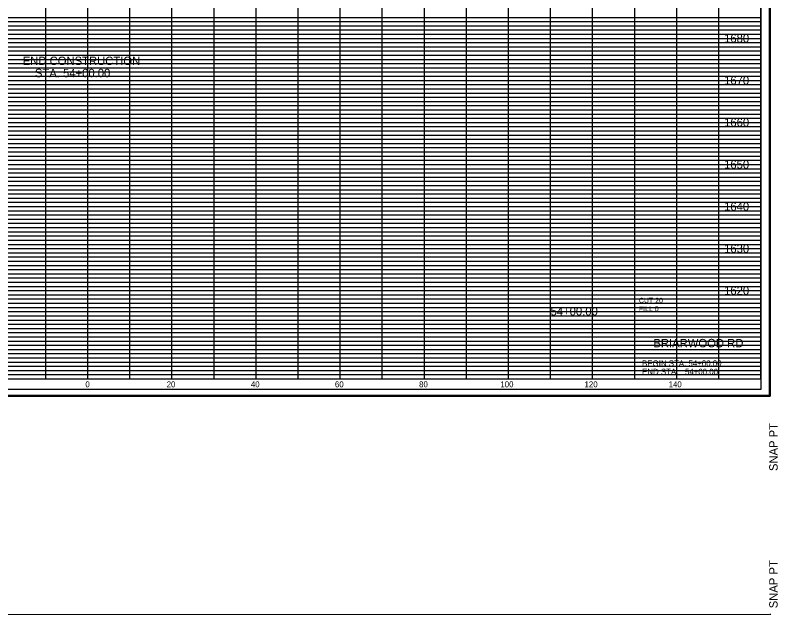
# Model space of a CAD drawing. Extents: x 980 to 2228, y 978 to 2394.
# Drawn here: x 1142.7 to 1324, y 2025.5 to 2166.5 of the extents above; entities that cross this region are included whole.
import ezdxf

# ---------------------------------------------------------------- set-up
doc = ezdxf.new("R2010")
doc.units = 0
for name, color, linetype in [('DESIGN - SHEET - Corner Text', 7, 'Continuous'), ('DESIGN - SHEET - Light Grid', 7, 'Continuous'), ('DESIGN - SHEET - Linework', 7, 'Continuous'), ('DESIGN - SHEET - Plot Shape', 7, 'Continuous'), ('DESIGN - TYPICAL - Finished Grade and Subgrade', 7, 'Continuous'), ('DESIGN - TYPICAL - Text', 7, 'Continuous')]:
    doc.layers.add(name, color=color, linetype=linetype)

# ---------------------------------------------------------------- blocks, each defined once
blk = doc.blocks.new('XSTSHT')
at = {"layer": 'DESIGN - SHEET - Light Grid'}
for p, q in [((8, 8.6), (16, 8.6)), ((16, 8.6), (24, 8.6)), ((24, 8.6), (32, 8.6)), ((8, 8.5), (16, 8.5)), ((8, 8.4), (16, 8.4)), ((16, 8.5), (24, 8.5)), ((16, 8.4), (24, 8.4)), ((24, 8.5), (32, 8.5)), ((24, 8.4), (32, 8.4)), ((8, 8.3), (16, 8.3)), ((8, 8.2), (16, 8.2)), ((16, 8.3), (24, 8.3)), ((16, 8.2), (24, 8.2)), ((24, 8.3), (32, 8.3)), ((24, 8.2), (32, 8.2)), ((8, 8.1), (16, 8.1)), ((16, 8.1), (24, 8.1)), ((24, 8.1), (32, 8.1)), ((8, 7.9), (16, 7.9)), ((8, 7.8), (16, 7.8)), ((16, 7.9), (24, 7.9)), ((16, 7.8), (24, 7.8)), ((24, 7.9), (32, 7.9)), ((24, 7.8), (32, 7.8)), ((8, 7.7), (16, 7.7)), ((16, 7.7), (24, 7.7)), ((24, 7.7), (32, 7.7)), ((8, 7.6), (16, 7.6)), ((8, 7.5), (16, 7.5)), ((16, 7.6), (24, 7.6)), ((16, 7.5), (24, 7.5)), ((24, 7.6), (32, 7.6)), ((24, 7.5), (32, 7.5)), ((8, 7.4), (16, 7.4)), ((8, 7.3), (16, 7.3)), ((16, 7.4), (24, 7.4)), ((16, 7.3), (24, 7.3)), ((24, 7.4), (32, 7.4)), ((24, 7.3), (32, 7.3)), ((8, 7.2), (16, 7.2)), ((8, 7.1), (16, 7.1)), ((16, 7.2), (24, 7.2)), ((16, 7.1), (24, 7.1)), ((24, 7.2), (32, 7.2)), ((24, 7.1), (32, 7.1)), ((8, 6.9), (16, 6.9)), ((16, 6.9), (24, 6.9)), ((24, 6.9), (32, 6.9)), ((8, 6.8), (16, 6.8)), ((16, 6.8), (24, 6.8)), ((24, 6.8), (32, 6.8)), ((8, 6.7), (16, 6.7)), ((8, 6.6), (16, 6.6)), ((16, 6.7), (24, 6.7)), ((16, 6.6), (24, 6.6)), ((24, 6.7), (32, 6.7)), ((24, 6.6), (32, 6.6)), ((8, 6.5), (16, 6.5)), ((8, 6.4), (16, 6.4)), ((16, 6.5), (24, 6.5)), ((16, 6.4), (24, 6.4)), ((24, 6.5), (32, 6.5)), ((24, 6.4), (32, 6.4)), ((8, 6.3), (16, 6.3)), ((8, 6.2), (16, 6.2)), ((16, 6.3), (24, 6.3)), ((16, 6.2), (24, 6.2)), ((24, 6.3), (32, 6.3)), ((24, 6.2), (32, 6.2)), ((8, 6.1), (16, 6.1)), ((16, 6.1), (24, 6.1)), ((24, 6.1), (32, 6.1)), ((8, 5.9), (16, 5.9)), ((16, 5.9), (24, 5.9)), ((24, 5.9), (32, 5.9)), ((8, 5.8), (16, 5.8)), ((8, 5.7), (16, 5.7)), ((16, 5.8), (24, 5.8)), ((16, 5.7), (24, 5.7)), ((24, 5.8), (32, 5.8)), ((24, 5.7), (32, 5.7)), ((8, 5.6), (16, 5.6)), ((8, 5.5), (16, 5.5)), ((16, 5.6), (24, 5.6)), ((16, 5.5), (24, 5.5)), ((24, 5.6), (32, 5.6)), ((24, 5.5), (32, 5.5)), ((8, 5.4), (16, 5.4)), ((8, 5.3), (16, 5.3)), ((16, 5.4), (24, 5.4)), ((16, 5.3), (24, 5.3)), ((24, 5.4), (32, 5.4)), ((24, 5.3), (32, 5.3)), ((8, 5.2), (16, 5.2)), ((8, 5.1), (16, 5.1)), ((16, 5.2), (24, 5.2)), ((16, 5.1), (24, 5.1)), ((24, 5.2), (32, 5.2)), ((24, 5.1), (32, 5.1)), ((8, 4.9), (16, 4.9)), ((16, 4.9), (24, 4.9)), ((24, 4.9), (32, 4.9)), ((8, 4.8), (16, 4.8)), ((16, 4.8), (24, 4.8)), ((24, 4.8), (32, 4.8)), ((8, 4.7), (16, 4.7)), ((8, 4.6), (16, 4.6)), ((16, 4.7), (24, 4.7)), ((16, 4.6), (24, 4.6)), ((24, 4.7), (32, 4.7)), ((24, 4.6), (32, 4.6)), ((8, 4.5), (16, 4.5)), ((8, 4.4), (16, 4.4)), ((16, 4.5), (24, 4.5)), ((16, 4.4), (24, 4.4)), ((24, 4.5), (32, 4.5)), ((24, 4.4), (32, 4.4)), ((8, 4.3), (16, 4.3)), ((8, 4.2), (16, 4.2)), ((16, 4.3), (24, 4.3)), ((16, 4.2), (24, 4.2)), ((24, 4.3), (32, 4.3)), ((24, 4.2), (32, 4.2)), ((8, 4.1), (16, 4.1)), ((16, 4.1), (24, 4.1)), ((24, 4.1), (32, 4.1)), ((8, 3.9), (16, 3.9)), ((16, 3.9), (24, 3.9)), ((24, 3.9), (32, 3.9)), ((8, 3.8), (16, 3.8)), ((8, 3.7), (16, 3.7)), ((16, 3.8), (24, 3.8)), ((16, 3.7), (24, 3.7)), ((24, 3.8), (32, 3.8)), ((24, 3.7), (32, 3.7)), ((8, 3.6), (16, 3.6)), ((8, 3.5), (16, 3.5)), ((16, 3.6), (24, 3.6)), ((16, 3.5), (24, 3.5)), ((24, 3.6), (32, 3.6)), ((24, 3.5), (32, 3.5)), ((8, 3.4), (16, 3.4)), ((8, 3.3), (16, 3.3)), ((16, 3.4), (24, 3.4)), ((16, 3.3), (24, 3.3)), ((24, 3.4), (32, 3.4)), ((24, 3.3), (32, 3.3)), ((8, 3.2), (16, 3.2)), ((8, 3.1), (16, 3.1)), ((16, 3.2), (24, 3.2)), ((16, 3.1), (24, 3.1)), ((24, 3.2), (32, 3.2)), ((24, 3.1), (32, 3.1)), ((8, 2.9), (16, 2.9)), ((8, 2.8), (16, 2.8)), ((16, 2.9), (24, 2.9)), ((16, 2.8), (24, 2.8)), ((24, 2.9), (32, 2.9)), ((24, 2.8), (32, 2.8)), ((8, 2.7), (16, 2.7)), ((8, 2.6), (16, 2.6)), ((16, 2.7), (24, 2.7)), ((16, 2.6), (24, 2.6)), ((24, 2.7), (32, 2.7)), ((24, 2.6), (32, 2.6)), ((8, 2.5), (16, 2.5)), ((8, 2.4), (16, 2.4)), ((16, 2.5), (24, 2.5)), ((16, 2.4), (24, 2.4)), ((24, 2.5), (32, 2.5)), ((24, 2.4), (32, 2.4)), ((8, 2.3), (16, 2.3)), ((8, 2.2), (16, 2.2)), ((16, 2.3), (24, 2.3)), ((16, 2.2), (24, 2.2)), ((24, 2.3), (32, 2.3)), ((24, 2.2), (32, 2.2)), ((8, 2.1), (16, 2.1)), ((16, 2.1), (24, 2.1)), ((24, 2.1), (32, 2.1)), ((8, 1.9), (16, 1.9)), ((16, 1.9), (24, 1.9)), ((24, 1.9), (32, 1.9)), ((8, 1.8), (16, 1.8)), ((8, 1.7), (16, 1.7)), ((16, 1.8), (24, 1.8)), ((16, 1.7), (24, 1.7)), ((24, 1.8), (32, 1.8)), ((24, 1.7), (32, 1.7)), ((8, 1.6), (16, 1.6)), ((8, 1.5), (16, 1.5)), ((16, 1.6), (24, 1.6)), ((16, 1.5), (24, 1.5)), ((24, 1.6), (32, 1.6)), ((24, 1.5), (32, 1.5)), ((8, 1.4), (16, 1.4)), ((8, 1.3), (16, 1.3)), ((16, 1.4), (24, 1.4)), ((16, 1.3), (24, 1.3)), ((24, 1.4), (32, 1.4)), ((24, 1.3), (32, 1.3)), ((8, 1.2), (16, 1.2)), ((8, 1.1), (16, 1.1)), ((16, 1.2), (24, 1.2)), ((16, 1.1), (24, 1.1)), ((24, 1.2), (32, 1.2)), ((24, 1.1), (32, 1.1)), ((8, 0.9), (16, 0.9)), ((8, 0.8), (16, 0.8)), ((16, 0.9), (24, 0.9)), ((16, 0.8), (24, 0.8)), ((24, 0.9), (32, 0.9)), ((24, 0.8), (32, 0.8)), ((8, 0.7), (16, 0.7)), ((8, 0.6), (16, 0.6)), ((16, 0.7), (24, 0.7)), ((16, 0.6), (24, 0.6)), ((24, 0.7), (32, 0.7)), ((24, 0.6), (32, 0.6)), ((8, 0.5), (16, 0.5)), ((8, 0.4), (16, 0.4)), ((16, 0.5), (24, 0.5)), ((16, 0.4), (24, 0.4)), ((24, 0.5), (32, 0.5)), ((24, 0.4), (32, 0.4)), ((8, 0.3), (16, 0.3)), ((8, 0.2), (16, 0.2)), ((16, 0.3), (24, 0.3)), ((16, 0.2), (24, 0.2)), ((24, 0.3), (32, 0.3)), ((24, 0.2), (32, 0.2)), ((8, 0.1), (16, 0.1)), ((16, 0.1), (24, 0.1)), ((24, 0.1), (32, 0.1))]:
    blk.add_line(p, q, dxfattribs=at)
at = {"layer": 'DESIGN - SHEET - Linework'}
for p, q in [((32.217, 21.414), (32.217, -0.414)), ((15, 0), (15, 21)), ((16, 0), (16, 21)), ((17, 0), (17, 21)), ((18, 0), (18, 21)), ((19, 0), (19, 21)), ((20, 0), (20, 21)), ((21, 0), (21, 21)), ((22, 0), (22, 21)), ((23, 0), (23, 21)), ((24, 0), (24, 21)), ((25, 0), (25, 21)), ((26, 0), (26, 21)), ((27, 0), (27, 21)), ((28, 0), (28, 20)), ((29, 0), (29, 20)), ((30, 0), (30, 20)), ((31, 0), (31, 20)), ((0, 8), (32, 8)), ((0, 7), (32, 7)), ((0, 6), (32, 6)), ((0, 5), (32, 5)), ((0, 4), (32, 4)), ((0, 3), (32, 3)), ((0, 2), (32, 2)), ((0, 1), (32, 1)), ((-1.823, -0.414), (32.217, -0.414))]:
    blk.add_line(p, q, dxfattribs=at)
blk.add_lwpolyline([(0, 21), (0, 0), (32, 0), (32, 21), (0, 21)], dxfattribs=at)
at = {"layer": 'DESIGN - SHEET - Plot Shape'}
for points in [[(-1.803, 21.394), (32.197, 21.394), (32.197, -0.394), (-1.803, -0.394)], [(-0.85, 21), (32, 21), (32, -0.25), (-0.85, -0.25)]]:
    blk.add_lwpolyline(points, close=True, dxfattribs=at)
at = {"layer": 'DESIGN - SHEET - Corner Text'}
for s, p in [('  SNAP PT', (32.397, 21.394)), ('SNAP PT  ', (32.397, -2.194))]:
    blk.add_text(s, height=0.2, rotation=90, dxfattribs=at).set_placement(p)

msp = doc.modelspace()

# ---------------------------------------------------------------- linework, layer by layer
at = {"layer": 'DESIGN - SHEET - Plot Shape'}
msp.add_lwpolyline([(991.5, 2290), (1320, 2290), (1320, 2077.5), (991.5, 2077.5)], close=True, dxfattribs=at)

# ---------------------------------------------------------------- block references
at = {"layer": 'DESIGN - TYPICAL - Finished Grade and Subgrade', "xscale": 10, "yscale": 10}
for p in [(1000, 2080), (1000, 1810)]:
    msp.add_blockref('XSTSHT', p, dxfattribs=at)

# ---------------------------------------------------------------- texts
at = {"layer": 'DESIGN - SHEET - Corner Text'}
for s, height, p in [('1680', 2, (1311.25, 2160)), ('1670', 2, (1311.25, 2150)), ('1660', 2, (1311.25, 2140)), ('1650', 2, (1311.25, 2130)), ('1640', 2, (1311.25, 2120)), ('1630', 2, (1311.25, 2110)), ('1620', 2, (1311.25, 2100)), ('BRIARWOOD RD', 2, (1294.44, 2087.5)), ('BEGIN STA. 54+00.00', 1.4, (1291.75, 2083)), ('END STA.   54+00.00', 1.4, (1291.75, 2081)), ('0', 1.4, (1159.42, 2078)), ('0', 1.4, (1159.42, 2078)), ('20', 1.4, (1178.74, 2078)), ('40', 1.4, (1198.74, 2078)), ('60', 1.4, (1218.74, 2078)), ('80', 1.4, (1238.74, 2078)), ('100', 1.4, (1258.06, 2078)), ('120', 1.4, (1278.06, 2078)), ('140', 1.4, (1298.06, 2078))]:
    msp.add_text(s, height=height, dxfattribs=at).set_placement(p)
at = {"layer": 'DESIGN - TYPICAL - Text'}
for s, height, p in [('END CONSTRUCTION', 2, (1144.52, 2154.65)), ('STA. 54+00.00', 2, (1147.42, 2151.75)), ('CUT 20', 1.2, (1291, 2098.08)), ('54+00.00', 2, (1270, 2095.08)), ('FILL 0', 1.2, (1291, 2096.08))]:
    msp.add_text(s, height=height, dxfattribs=at).set_placement(p)

doc.saveas('drawing.dxf')
